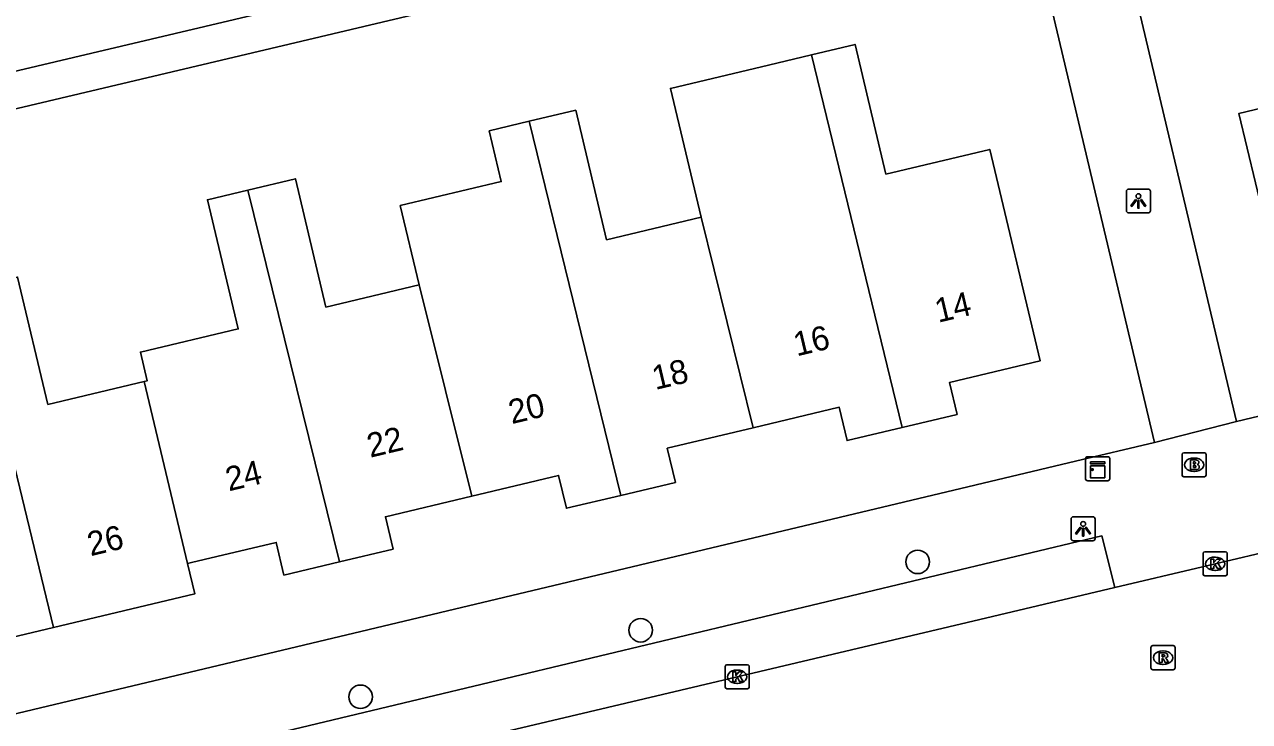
# Model space of a CAD drawing. Extents: x 158038 to 159242, y 380133 to 381214.
# Drawn here: x 158523.4 to 158574.3, y 380695.7 to 380724.7 of the extents above; entities that cross this region are included whole.
import ezdxf

# ---------------------------------------------------------------- set-up
doc = ezdxf.new("R2010")
doc.units = 0
for name, color, linetype in [('IMGEO_Boom', 7, 'Continuous'), ('IMGEO_Brandkraan', 7, 'Continuous'), ('IMGEO_Kast', 7, 'Continuous'), ('IMGEO_Kolk', 7, 'Continuous'), ('IMGEO_Lichtpunt', 7, 'Continuous'), ('IMGEO_Pand', 7, 'Continuous'), ('IMGEO_Pand_nummerreeks', 7, 'Continuous'), ('IMGEO_Rijbaan_lokaal_gesloten', 7, 'Continuous'), ('IMGEO_Rioolput', 7, 'Continuous'), ('IMGEO_Voetpad_open', 7, 'Continuous')]:
    doc.layers.add(name, color=color, linetype=linetype)

msp = doc.modelspace()

# ---------------------------------------------------------------- linework, layer by layer
at = {"layer": 'IMGEO_Boom'}
for centre in [(158560.511, 380702.333), (158549.003, 380699.492), (158537.368, 380696.726)]:
    msp.add_circle(centre, 0.489, dxfattribs=at)
at = {"layer": 'IMGEO_Brandkraan'}
for p, q in [((158571.493, 380705.941), (158571.493, 380706.793)), ((158571.568, 380706.867), (158572.42, 380706.867)), ((158571.981, 380706.647), (158572.006, 380706.647)), ((158572.494, 380706.793), (158572.494, 380705.941)), ((158572.004, 380706.087), (158571.979, 380706.087)), ((158572.42, 380705.867), (158571.568, 380705.867))]:
    msp.add_line(p, q, dxfattribs=at)
for points in [[(158571.493, 380705.941), (158571.493, 380706.793)], [(158571.568, 380706.867), (158572.42, 380706.867)], [(158572.494, 380706.793), (158572.494, 380705.941)], [(158571.841, 380706.567), (158571.841, 380706.167), (158572.054, 380706.167)], [(158572.072, 380706.567), (158571.841, 380706.567)], [(158572.02, 380706.486), (158571.966, 380706.486), (158571.966, 380706.41)], [(158571.966, 380706.41), (158572.019, 380706.41)], [(158572.028, 380706.334), (158571.966, 380706.334), (158571.966, 380706.253)], [(158571.966, 380706.253), (158572.028, 380706.253)], [(158572.42, 380705.867), (158571.568, 380705.867)]]:
    msp.add_lwpolyline(points, dxfattribs=at)
for centre, radius, start, end in [((158571.57, 380706.791), 0.0765, 91.552, 178.448), ((158571.57, 380706.791), 0.0765, 91.552, 178.448), ((158572.418, 380706.791), 0.0765, 1.552, 88.448), ((158572.418, 380706.791), 0.0765, 1.552, 88.448), ((158572.021, 380706.448), 0.0379, 267.8285, 90.9355), ((158572.029, 380706.293), 0.0404, 269.8759, 90.5077), ((158572.06, 380706.418), 0.251, 268.6676, 293.5347), ((158572.076, 380706.422), 0.145, 59.4692, 91.5367), ((158572.101, 380706.469), 0.0922, 285.5137, 58.1501), ((158572.106, 380706.277), 0.105, 301.3115, 78.989), ((158571.57, 380705.943), 0.0765, 181.552, 268.448), ((158571.57, 380705.943), 0.0765, 181.552, 268.448), ((158572.418, 380705.943), 0.0765, 271.552, 358.448), ((158572.418, 380705.943), 0.0765, 271.552, 358.448)]:
    msp.add_arc(centre, radius, start, end, dxfattribs=at)
for centre, major_axis, ratio, start_param, end_param in [((158571.98, 380706.367), (-0.387, 0.002), 0.722429, 4.712389, 7.853982), ((158572.005, 380706.367), (-0.39, 0.002), 0.717154, 1.570796, 4.712389)]:
    msp.add_ellipse(centre, major_axis=major_axis, ratio=ratio, start_param=start_param, end_param=end_param, dxfattribs=at)
at = {"layer": 'IMGEO_Kast'}
for p, q in [((158567.488, 380705.779), (158567.488, 380706.62)), ((158567.488, 380706.62), (158567.488, 380705.779)), ((158567.563, 380706.704), (158568.404, 380706.704)), ((158568.404, 380706.704), (158567.563, 380706.704)), ((158568.488, 380706.629), (158568.488, 380705.788)), ((158568.488, 380705.788), (158568.488, 380706.629)), ((158568.413, 380705.704), (158567.572, 380705.704)), ((158567.572, 380705.704), (158568.413, 380705.704))]:
    msp.add_line(p, q, dxfattribs=at)
for points in [[(158567.683, 380706.494), (158568.283, 380706.494), (158568.283, 380706.409), (158567.683, 380706.409), (158567.683, 380706.494)], [(158567.683, 380706.319), (158568.283, 380706.319), (158568.283, 380705.83), (158567.683, 380705.83), (158567.683, 380706.319)]]:
    msp.add_lwpolyline(points, dxfattribs=at)
msp.add_circle((158567.767, 380706.168), 0.0377, dxfattribs=at)
for centre, start, end in [((158567.566, 380706.626), 92.4484, 184.2845), ((158567.566, 380706.626), 92.4484, 184.2845), ((158568.41, 380706.626), 2.4484, 94.2845), ((158568.41, 380706.626), 2.4484, 94.2845), ((158567.566, 380705.782), 182.4484, 274.2845), ((158567.566, 380705.782), 182.4484, 274.2845), ((158568.41, 380705.782), 272.4484, 4.2845), ((158568.41, 380705.782), 272.4484, 4.2845)]:
    msp.add_arc(centre, 0.0779, start, end, dxfattribs=at)
at = {"layer": 'IMGEO_Kolk'}
for p, q in [((158572.367, 380701.826), (158572.367, 380702.678)), ((158572.442, 380702.752), (158573.294, 380702.752)), ((158572.855, 380702.532), (158572.88, 380702.532)), ((158573.368, 380702.678), (158573.368, 380701.826)), ((158573.294, 380701.752), (158572.442, 380701.752)), ((158572.878, 380701.972), (158572.853, 380701.972)), ((158552.513, 380697.132), (158552.513, 380697.984)), ((158552.588, 380698.058), (158553.44, 380698.058)), ((158553.514, 380697.984), (158553.514, 380697.132)), ((158553.001, 380697.838), (158553.026, 380697.838)), ((158553.44, 380697.058), (158552.588, 380697.058)), ((158553.024, 380697.278), (158552.999, 380697.278))]:
    msp.add_line(p, q, dxfattribs=at)
for points in [[(158572.367, 380701.826), (158572.367, 380702.678)], [(158572.442, 380702.752), (158573.294, 380702.752)], [(158573.368, 380702.678), (158573.368, 380701.826)], [(158572.688, 380702.452), (158572.811, 380702.452), (158572.811, 380702.301), (158572.941, 380702.452), (158573.105, 380702.452), (158572.959, 380702.301), (158573.112, 380702.052), (158572.96, 380702.052), (158572.875, 380702.216), (158572.811, 380702.149), (158572.811, 380702.052), (158572.688, 380702.052), (158572.688, 380702.452)], [(158573.294, 380701.752), (158572.442, 380701.752)], [(158552.513, 380697.132), (158552.513, 380697.984)], [(158552.588, 380698.058), (158553.44, 380698.058)], [(158553.514, 380697.984), (158553.514, 380697.132)], [(158552.834, 380697.758), (158552.957, 380697.758), (158552.957, 380697.607), (158553.087, 380697.758), (158553.251, 380697.758), (158553.105, 380697.607), (158553.258, 380697.358), (158553.106, 380697.358), (158553.021, 380697.522), (158552.957, 380697.455), (158552.957, 380697.358), (158552.834, 380697.358), (158552.834, 380697.758)], [(158553.44, 380697.058), (158552.588, 380697.058)]]:
    msp.add_lwpolyline(points, dxfattribs=at)
for centre, start, end in [((158572.444, 380702.676), 91.552, 178.448), ((158572.444, 380702.676), 91.552, 178.448), ((158573.292, 380702.676), 1.552, 88.448), ((158573.292, 380702.676), 1.552, 88.448), ((158572.444, 380701.828), 181.552, 268.448), ((158572.444, 380701.828), 181.552, 268.448), ((158573.292, 380701.828), 271.552, 358.448), ((158573.292, 380701.828), 271.552, 358.448), ((158552.59, 380697.982), 91.552, 178.448), ((158552.59, 380697.982), 91.552, 178.448), ((158553.438, 380697.982), 1.552, 88.448), ((158553.438, 380697.982), 1.552, 88.448), ((158552.59, 380697.134), 181.552, 268.448), ((158552.59, 380697.134), 181.552, 268.448), ((158553.438, 380697.134), 271.552, 358.448), ((158553.438, 380697.134), 271.552, 358.448)]:
    msp.add_arc(centre, 0.0765, start, end, dxfattribs=at)
for centre, major_axis, ratio, start_param, end_param in [((158572.854, 380702.252), (-0.387, 0.002), 0.722429, 4.712389, 7.853982), ((158572.879, 380702.252), (-0.39, 0.002), 0.717154, 1.570796, 4.712389), ((158553, 380697.558), (-0.387, 0.002), 0.722429, 4.712389, 7.853982), ((158553.025, 380697.558), (-0.39, 0.002), 0.717154, 1.570796, 4.712389)]:
    msp.add_ellipse(centre, major_axis=major_axis, ratio=ratio, start_param=start_param, end_param=end_param, dxfattribs=at)
at = {"layer": 'IMGEO_Lichtpunt'}
for p, q in [((158570.083, 380717.828), (158569.275, 380717.828)), ((158570.083, 380717.828), (158569.275, 380717.828)), ((158569.181, 380717.733), (158569.181, 380716.926)), ((158569.181, 380717.733), (158569.181, 380716.926)), ((158570.177, 380716.926), (158570.177, 380717.733)), ((158570.177, 380716.926), (158570.177, 380717.733)), ((158569.275, 380716.832), (158570.083, 380716.832)), ((158569.275, 380716.832), (158570.083, 380716.832)), ((158566.885, 380704.113), (158566.885, 380703.306)), ((158566.885, 380704.113), (158566.885, 380703.306)), ((158567.787, 380704.208), (158566.979, 380704.208)), ((158567.787, 380704.208), (158566.979, 380704.208)), ((158567.881, 380703.306), (158567.881, 380704.113)), ((158567.881, 380703.306), (158567.881, 380704.113)), ((158566.979, 380703.212), (158567.787, 380703.212)), ((158566.979, 380703.212), (158567.787, 380703.212))]:
    msp.add_line(p, q, dxfattribs=at)
for points in [[(158569.555, 380717.397), (158569.594, 380717.369), (158569.406, 380717.107), (158569.368, 380717.134), (158569.555, 380717.397)], [(158569.657, 380717.349), (158569.704, 380717.349), (158569.704, 380717.027), (158569.657, 380717.027), (158569.657, 380717.349)], [(158569.767, 380717.369), (158569.805, 380717.396), (158569.992, 380717.134), (158569.953, 380717.106), (158569.767, 380717.369)], [(158567.259, 380703.777), (158567.298, 380703.749), (158567.11, 380703.487), (158567.072, 380703.514), (158567.259, 380703.777)], [(158567.361, 380703.729), (158567.408, 380703.729), (158567.408, 380703.407), (158567.361, 380703.407), (158567.361, 380703.729)], [(158567.471, 380703.749), (158567.509, 380703.776), (158567.696, 380703.514), (158567.657, 380703.486), (158567.471, 380703.749)]]:
    msp.add_lwpolyline(points, dxfattribs=at)
for centre in [(158569.68, 380717.531), (158567.384, 380703.911)]:
    msp.add_circle(centre, 0.0994, dxfattribs=at)
for centre, start, end in [((158569.275, 380717.733), 90, 180), ((158569.275, 380717.733), 90, 180), ((158570.083, 380717.733), 0, 90), ((158570.083, 380717.733), 0, 90), ((158569.275, 380716.926), 180, 270), ((158569.275, 380716.926), 180, 270), ((158570.083, 380716.926), 270, 0), ((158570.083, 380716.926), 270, 360), ((158566.979, 380704.113), 90, 180), ((158566.979, 380704.113), 90, 180), ((158567.787, 380704.113), 0, 90), ((158567.787, 380704.113), 0, 90), ((158566.979, 380703.306), 180, 270), ((158566.979, 380703.306), 180, 270), ((158567.787, 380703.306), 270, 0), ((158567.787, 380703.306), 270, 360)]:
    msp.add_arc(centre, 0.0946, start, end, dxfattribs=at)
at = {"layer": 'IMGEO_Pand'}
for points in [[(158581.991, 380713.766), (158575.924, 380712.316), (158573.855, 380720.969), (158578.181, 380722.003), (158576.88, 380727.444), (158578.685, 380727.875)], [(158556.096, 380723.402), (158554.309, 380722.977), (158550.237, 380722.009), (158551.511, 380716.657)], [(158559.87, 380707.921), (158562.15, 380708.464), (158561.835, 380709.788), (158565.595, 380710.683), (158563.503, 380719.471), (158559.192, 380718.445), (158557.909, 380723.834), (158556.096, 380723.402)], [(158556.096, 380723.402), (158559.87, 380707.921)], [(158544.373, 380720.64), (158546.305, 380721.1), (158547.586, 380715.722), (158551.511, 380716.657)], [(158544.373, 380720.64), (158542.713, 380720.245), (158543.215, 380718.138), (158539.017, 380717.139), (158539.801, 380713.845)], [(158548.179, 380705.098), (158544.373, 380720.64)], [(158532.684, 380717.783), (158531.006, 380717.383), (158532.284, 380712.015), (158528.224, 380711.048), (158528.507, 380709.858), (158528.378, 380709.827)], [(158532.684, 380717.783), (158534.659, 380718.253), (158535.929, 380712.923), (158539.801, 380713.845)], [(158536.487, 380702.331), (158532.684, 380717.783)], [(158551.511, 380716.657), (158553.68, 380707.906)], [(158528.378, 380709.827), (158524.382, 380708.876), (158523.122, 380714.167), (158521.188, 380713.706)], [(158521.188, 380713.706), (158524.618, 380699.608)], [(158539.801, 380713.845), (158541.989, 380705.066)], [(158528.378, 380709.827), (158530.184, 380702.264)], [(158553.68, 380707.906), (158557.251, 380708.757), (158557.58, 380707.376), (158559.87, 380707.921)], [(158553.68, 380707.906), (158550.109, 380707.056), (158550.447, 380705.638), (158548.179, 380705.098)], [(158541.989, 380705.066), (158545.592, 380705.924), (158545.917, 380704.559), (158548.179, 380705.098)], [(158541.989, 380705.066), (158538.398, 380704.211), (158538.719, 380702.862), (158536.487, 380702.331)], [(158530.184, 380702.264), (158530.342, 380702.302), (158531.404, 380702.555), (158533.864, 380703.14), (158534.187, 380701.783), (158536.487, 380702.331)], [(158524.618, 380699.608), (158530.484, 380701.008), (158530.184, 380702.264)], [(158524.618, 380699.608), (158518.779, 380698.214)]]:
    msp.add_lwpolyline(points, dxfattribs=at)
at = {"layer": 'IMGEO_Rijbaan_lokaal_gesloten'}
for points in [[(158568.7, 380701.266), (158575.987, 380702.987)], [(158568.7, 380701.266), (158562.571, 380699.819), (158542.058, 380694.963), (158511.485, 380687.697), (158500, 380684.965), (158478.511, 380679.852)]]:
    msp.add_lwpolyline(points, dxfattribs=at)
at = {"layer": 'IMGEO_Rioolput'}
for p, q in [((158570.201, 380697.926), (158570.201, 380698.778)), ((158570.276, 380698.852), (158571.128, 380698.852)), ((158570.689, 380698.632), (158570.714, 380698.632)), ((158571.202, 380698.778), (158571.202, 380697.926)), ((158570.712, 380698.072), (158570.687, 380698.072)), ((158571.128, 380697.852), (158570.276, 380697.852))]:
    msp.add_line(p, q, dxfattribs=at)
for points in [[(158570.201, 380697.926), (158570.201, 380698.778)], [(158570.276, 380698.852), (158571.128, 380698.852)], [(158570.79, 380698.55), (158570.538, 380698.552), (158570.538, 380698.152)], [(158570.716, 380698.471), (158570.662, 380698.471), (158570.662, 380698.39)], [(158571.202, 380698.778), (158571.202, 380697.926)], [(158570.538, 380698.152), (158570.662, 380698.152), (158570.662, 380698.314), (158570.673, 380698.314)], [(158570.662, 380698.39), (158570.714, 380698.39)], [(158570.72, 380698.285), (158570.791, 380698.152), (158570.931, 380698.152), (158570.866, 380698.278)], [(158571.128, 380697.852), (158570.276, 380697.852)]]:
    msp.add_lwpolyline(points, dxfattribs=at)
for centre, radius, start, end in [((158570.278, 380698.776), 0.0765, 91.552, 178.448), ((158570.278, 380698.776), 0.0765, 91.552, 178.448), ((158570.722, 380698.375), 0.0964, 77.0061, 93.1865), ((158570.736, 380698.432), 0.0378, 276.6634, 79.6772), ((158570.789, 380698.44), 0.109, 350.3612, 89.416), ((158571.126, 380698.776), 0.0765, 1.552, 88.448), ((158571.126, 380698.776), 0.0765, 1.552, 88.448), ((158570.278, 380697.928), 0.0765, 181.552, 268.448), ((158570.278, 380697.928), 0.0765, 181.552, 268.448), ((158570.672, 380698.261), 0.0533, 26.0293, 88.6989), ((158570.698, 380698.579), 0.19, 274.7715, 282.9687), ((158570.787, 380698.44), 0.112, 277.5842, 350.9817), ((158570.771, 380698.225), 0.108, 29.5134, 73.7905), ((158571.126, 380697.928), 0.0765, 271.552, 358.448), ((158571.126, 380697.928), 0.0765, 271.552, 358.448)]:
    msp.add_arc(centre, radius, start, end, dxfattribs=at)
for centre, major_axis, ratio, start_param, end_param in [((158570.688, 380698.352), (-0.387, 0.002), 0.722429, 4.712389, 7.853982), ((158570.713, 380698.352), (-0.39, 0.002), 0.717154, 1.570796, 4.712389)]:
    msp.add_ellipse(centre, major_axis=major_axis, ratio=ratio, start_param=start_param, end_param=end_param, dxfattribs=at)
at = {"layer": 'IMGEO_Voetpad_open'}
for points in [[(158515.725, 380742.86), (158520.628, 380722.152), (158526.203, 380723.472), (158552.37, 380729.668)], [(158564.728, 380731.038), (158521.04, 380720.689), (158521.442, 380718.991), (158480.571, 380709.28)], [(158570.352, 380707.295), (158564.728, 380731.038)], [(158568.508, 380730.343), (158573.761, 380708.16)], [(158615.556, 380718.152), (158573.761, 380708.16)], [(158573.761, 380708.16), (158570.352, 380707.295)], [(158570.352, 380707.295), (158567.068, 380706.513), (158500, 380690.536), (158478.148, 380685.33)], [(158478.511, 380679.852), (158478.741, 380679.951), (158478.961, 380680.07), (158479.169, 380680.209), (158479.365, 380680.365), (158479.545, 380680.538), (158479.71, 380680.727), (158479.795, 380680.84), (158480.211, 380681.743), (158480.258, 380681.855), (158480.323, 380681.978), (158480.398, 380682.096), (158480.484, 380682.206), (158480.579, 380682.308), (158480.683, 380682.401), (158480.795, 380682.485), (158480.913, 380682.558), (158481.038, 380682.62), (158481.168, 380682.671), (158481.302, 380682.71), (158481.439, 380682.737), (158500, 380687.103), (158568.163, 380703.411), (158568.7, 380701.266)]]:
    msp.add_lwpolyline(points, dxfattribs=at)

# ---------------------------------------------------------------- texts
at = {"layer": 'IMGEO_Pand_nummerreeks'}
for s, rotation, p in [('14', 13.3732, (158561.36, 380712.266)), ('16', 13.3728, (158555.484, 380710.869)), ('18', 13.3732, (158549.612, 380709.473)), ('20', 13.3728, (158543.647, 380708.055)), ('22', 13.3732, (158537.767, 380706.657)), ('24', 13.3728, (158531.893, 380705.261)), ('26', 13.4244, (158526.152, 380702.565))]:
    msp.add_text(s, height=1, rotation=rotation, dxfattribs=at).set_placement(p)

doc.saveas('drawing.dxf')
